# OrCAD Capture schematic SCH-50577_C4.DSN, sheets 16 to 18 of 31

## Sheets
16 16 PHY1_RGMII: size C
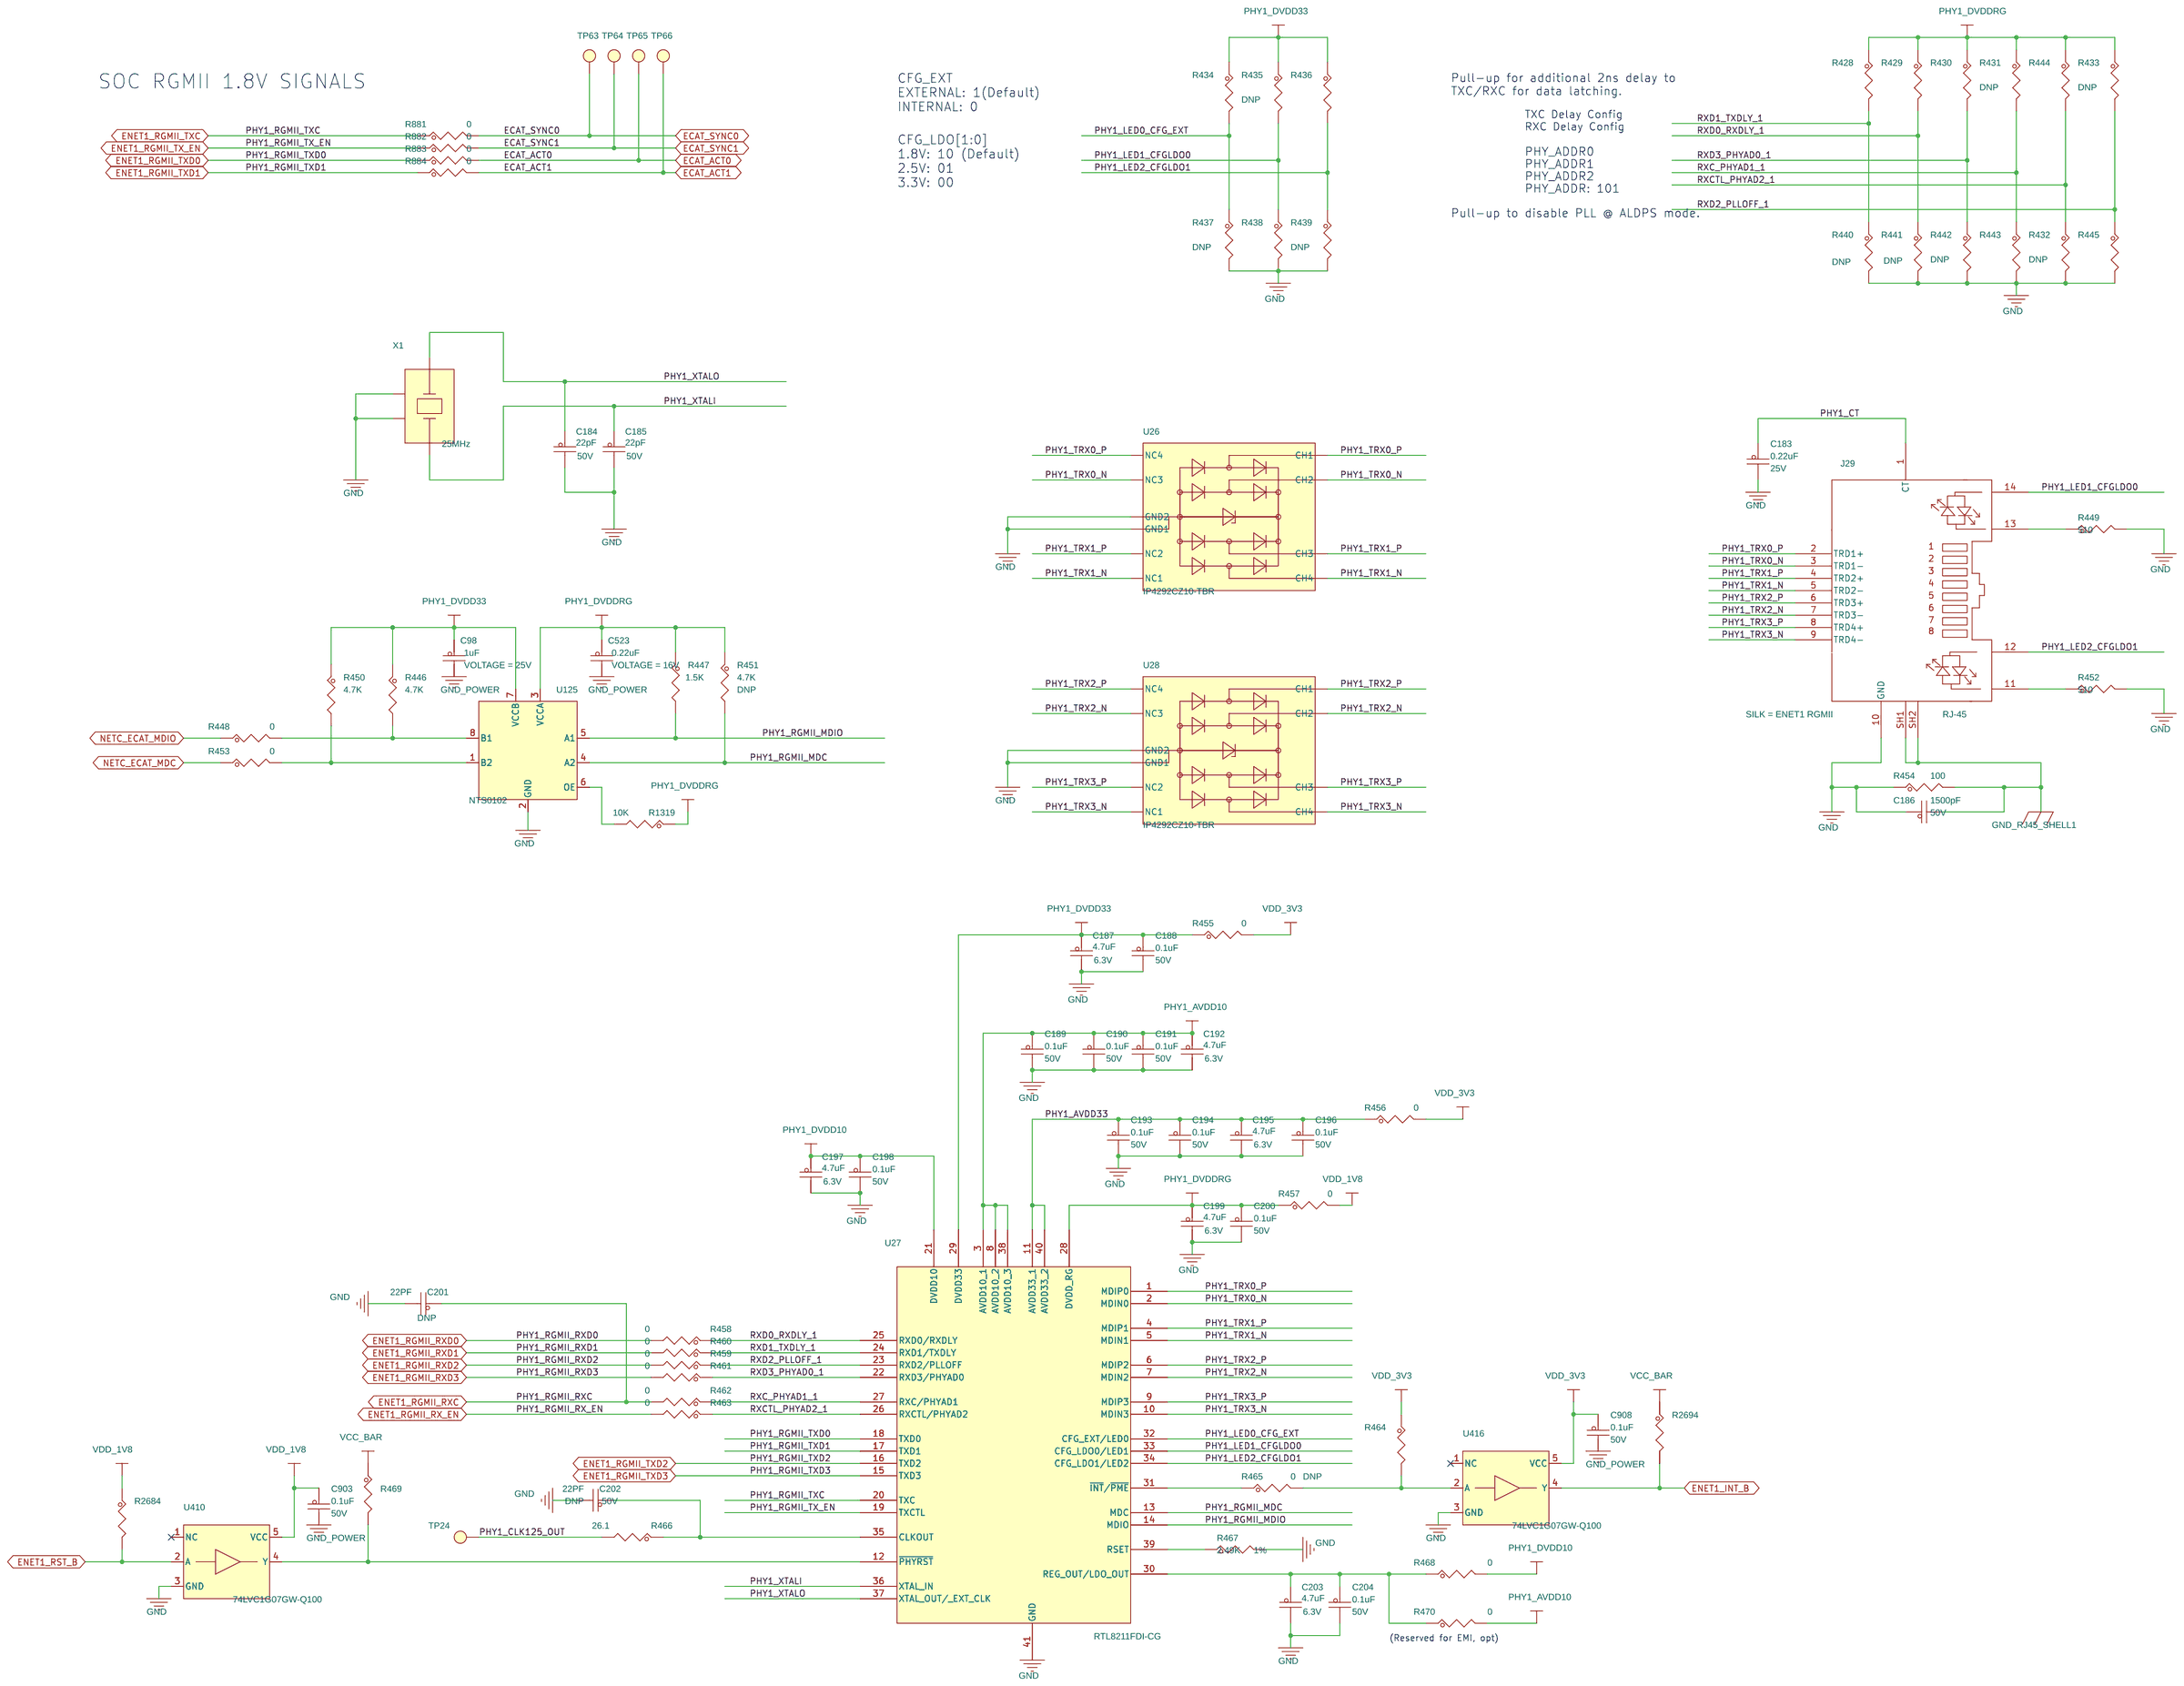
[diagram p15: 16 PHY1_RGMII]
17 17 PHY2_RGMII: size C
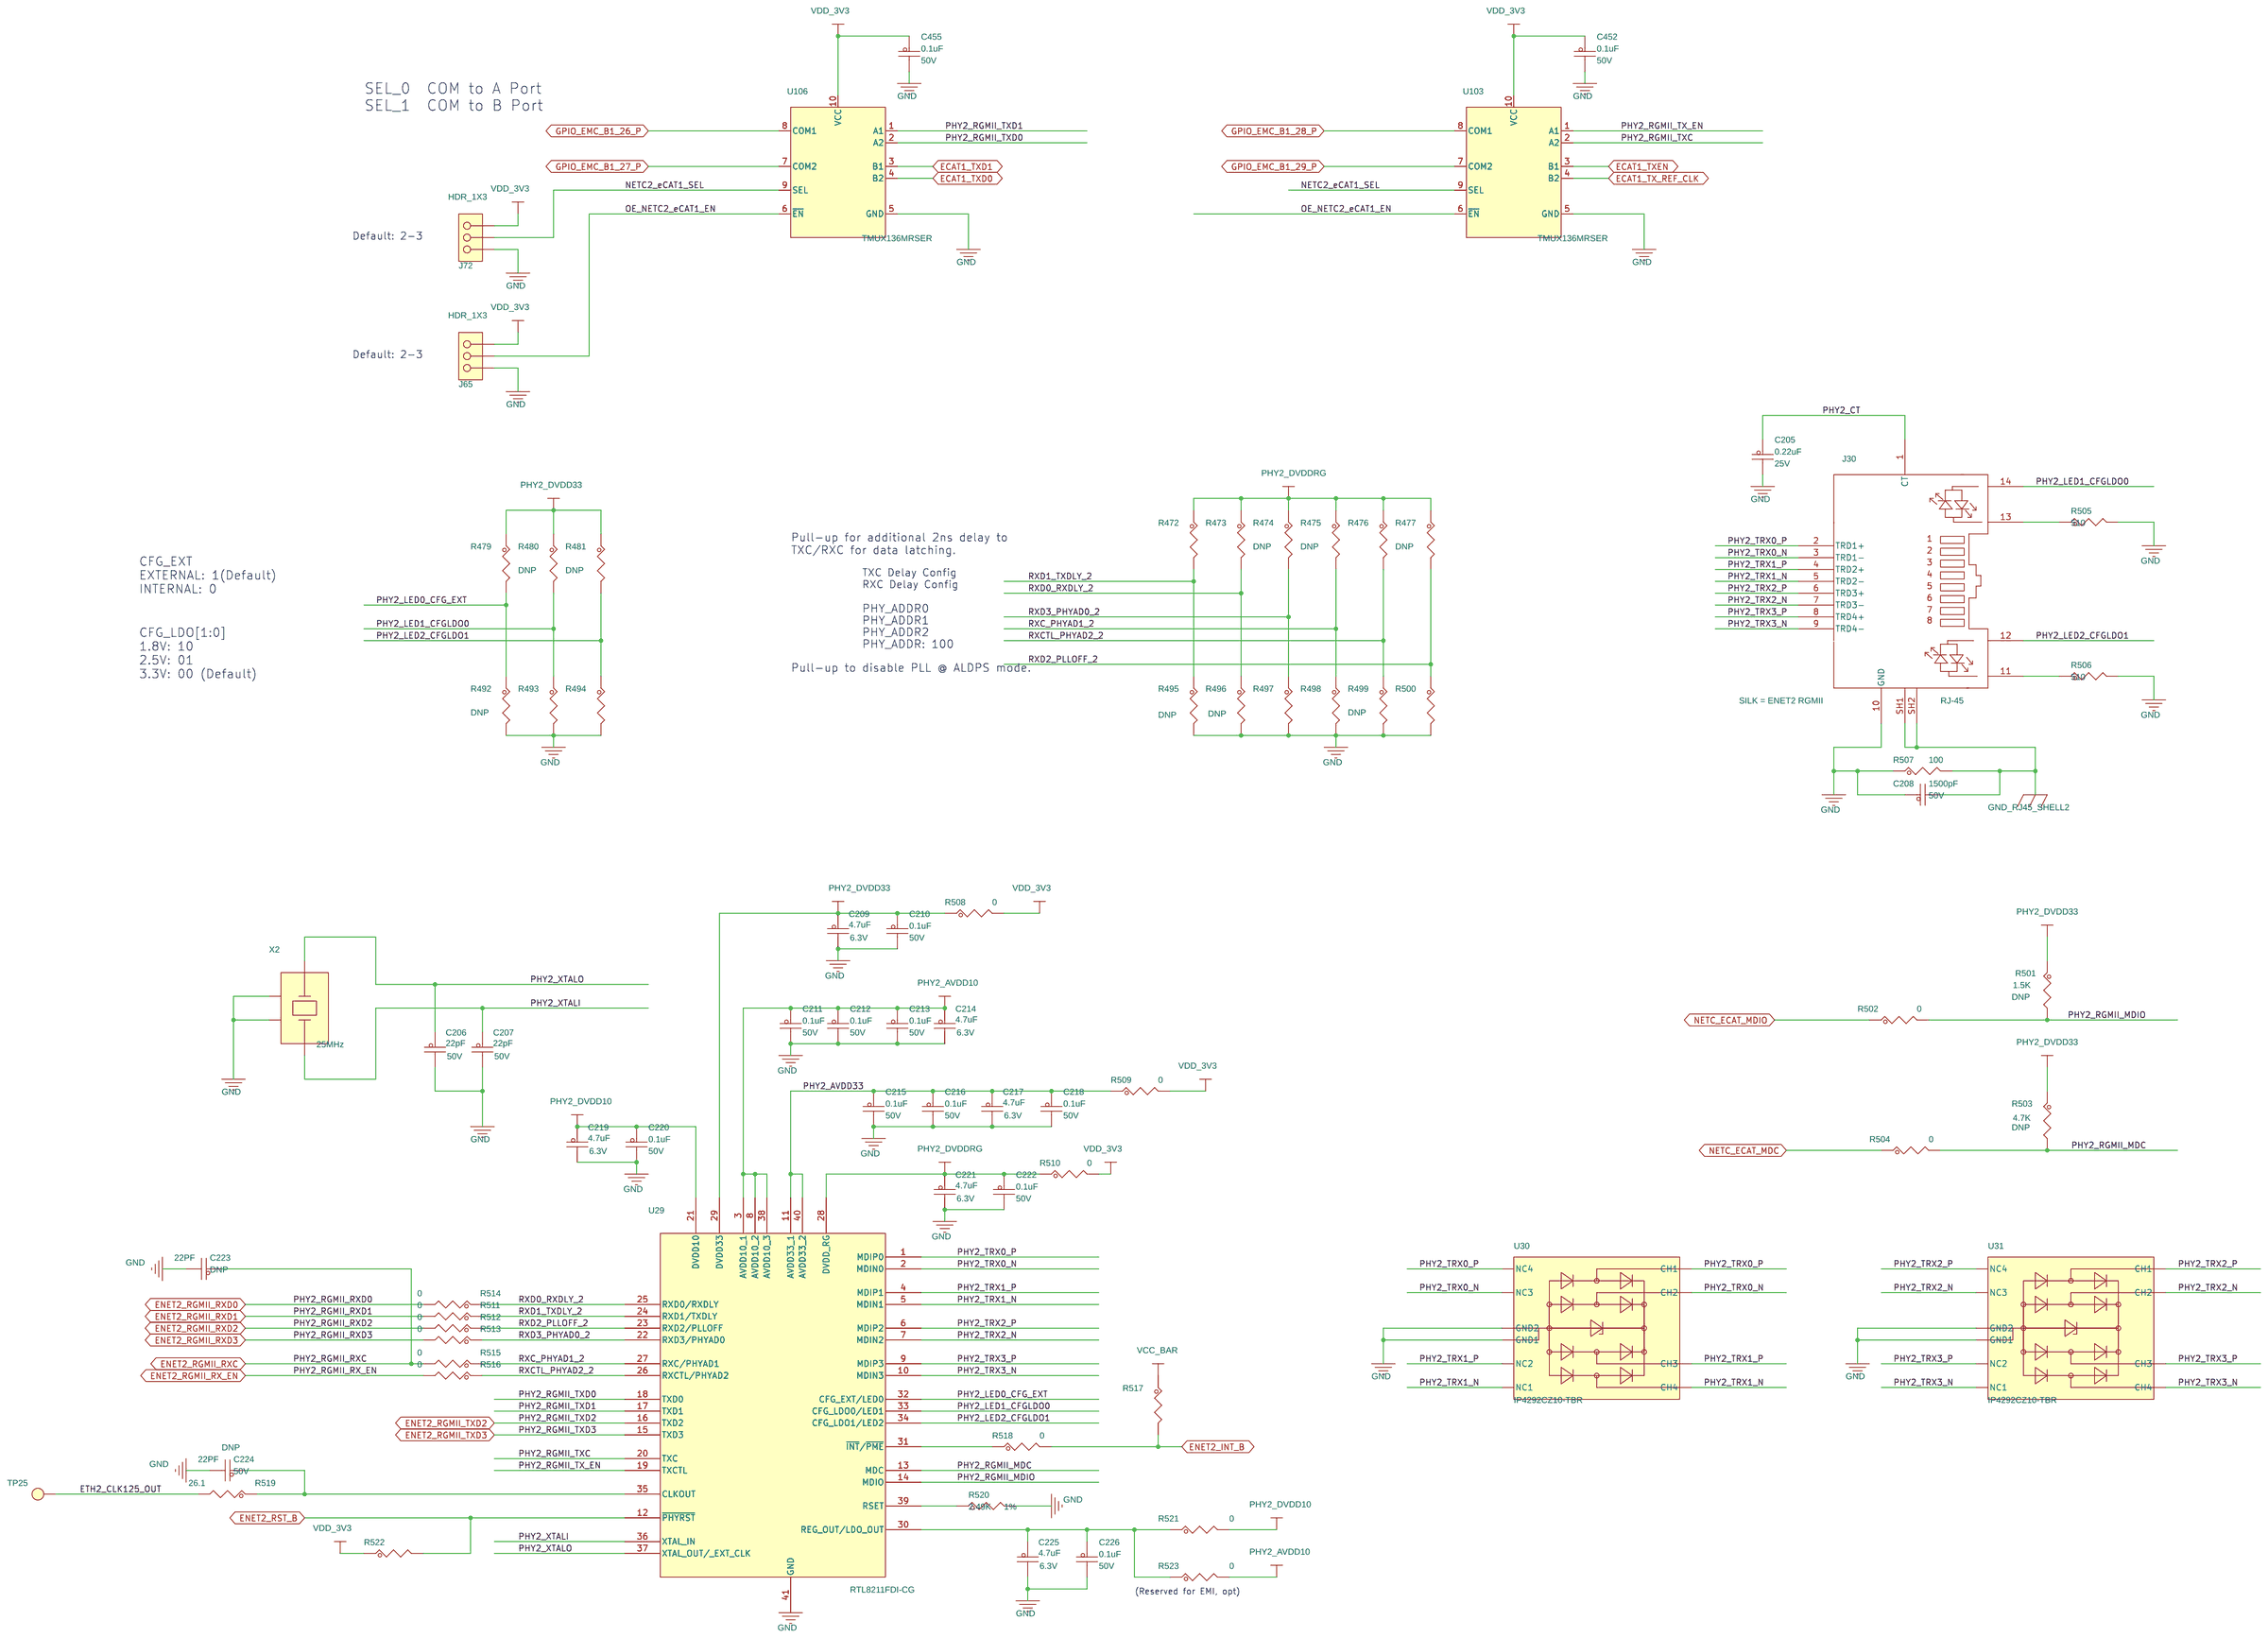
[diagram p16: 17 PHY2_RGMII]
18 18 PHY3_RGMII: size C
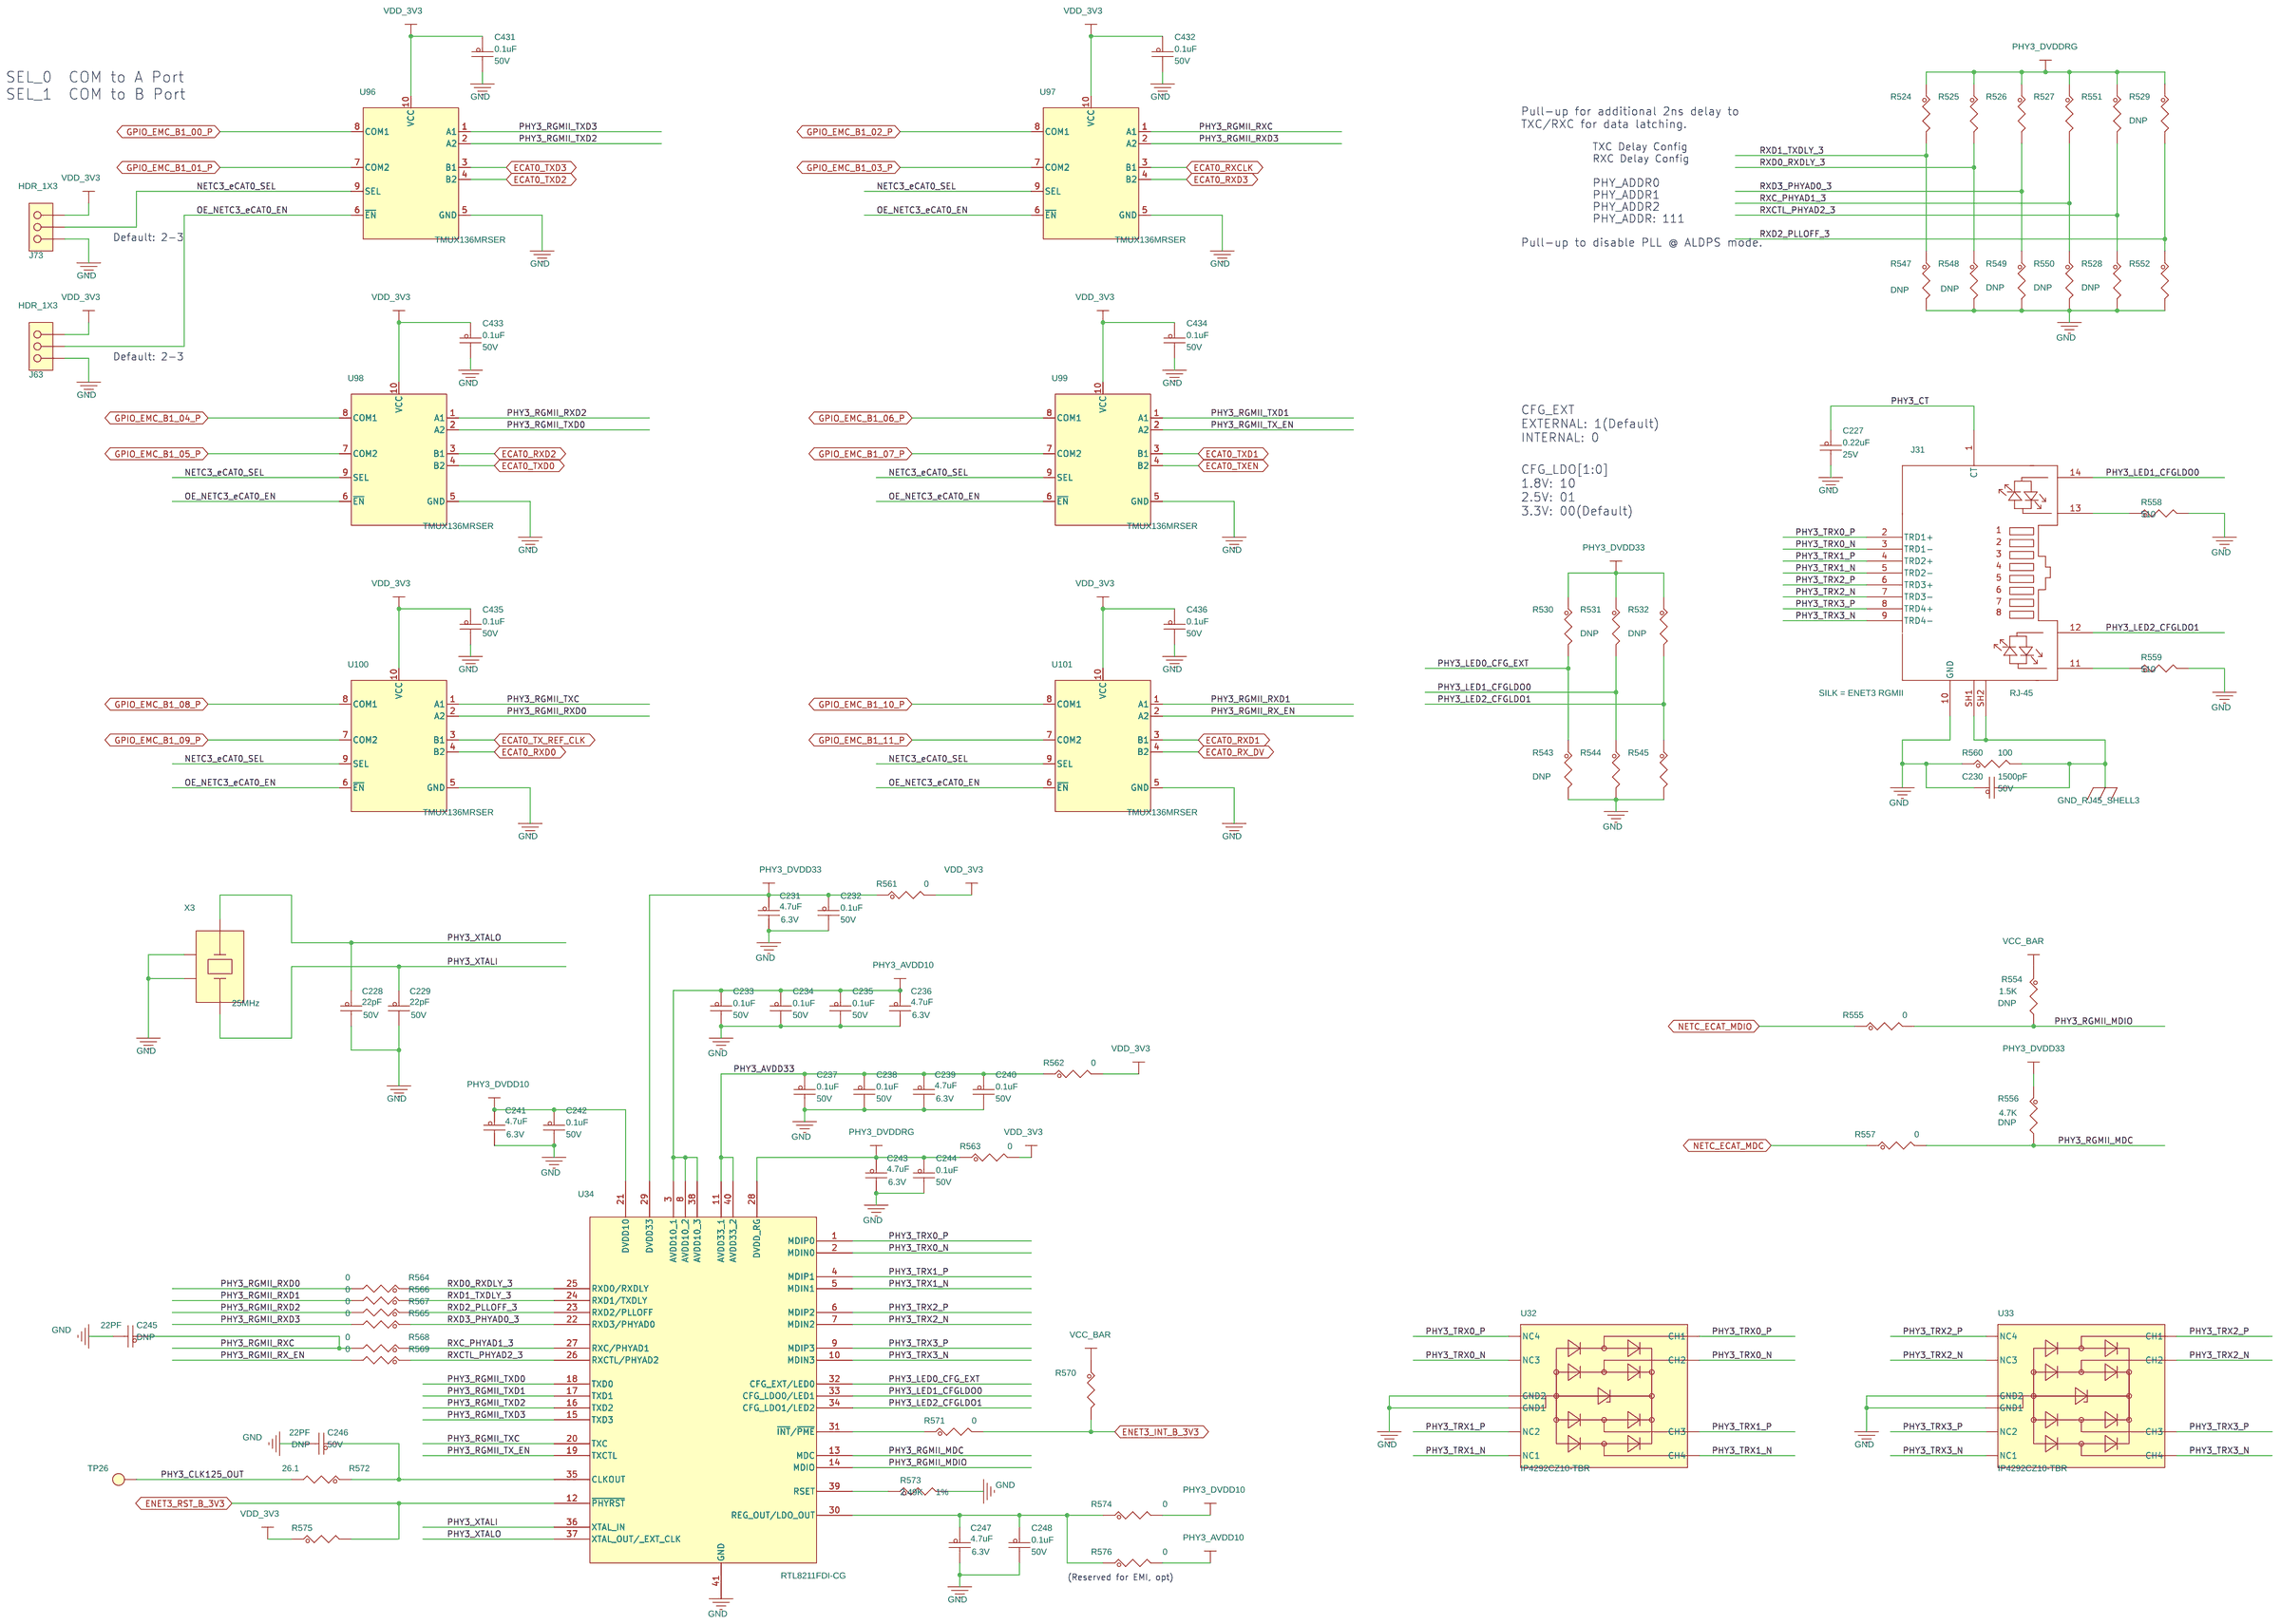
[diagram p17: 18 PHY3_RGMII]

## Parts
sheet 16 PHY1_RGMII
C98  1uF  [cc0402_tol0p2]
C183  0.22uF  [0402_CC]
C184  22pF  [0402_CC]
C185  22pF  [0402_CC]
C186  1500pF  [0402_CC]
C187  4.7uF  [cc0402_tol0p15]
C188  0.1uF  [0402_CC]
C189  0.1uF  [0402_CC]
C190  0.1uF  [0402_CC]
C191  0.1uF  [0402_CC]
C192  4.7uF  [cc0402_tol0p15]
C193  0.1uF  [0402_CC]
C194  0.1uF  [0402_CC]
C195  4.7uF  [cc0402_tol0p15]
C196  0.1uF  [0402_CC]
C197  4.7uF  [cc0402_tol0p15]
C198  0.1uF  [0402_CC]
C199  4.7uF  [cc0402_tol0p15]
C200  0.1uF  [0402_CC]
C201  22PF  [0402_CC]
C202  22PF  [0402_CC]
C203  4.7uF  [cc0402_tol0p15]
C204  0.1uF  [0402_CC]
C523  0.22uF  [0402_CC]
C903  0.1uF  [0402_CC]
C908  0.1uF  [0402_CC]
J29  RJ-45  [con_rj45_10_2led_th]
R428  4.7K  [0402_CC]
R429  4.7K  [0402_CC]
R430  4.7K  [0402_CC]
R431  4.7K  [0402_CC]
R432  4.7K  [0402_CC]
R433  4.7K  [0402_CC]
R434  4.7K  [0402_CC]
R435  4.7K  [0402_CC]
R436  4.7K  [0402_CC]
R437  4.7K  [0402_CC]
R438  4.7K  [0402_CC]
R439  4.7K  [0402_CC]
R440  4.7K  [0402_CC]
R441  4.7K  [0402_CC]
R442  4.7K  [0402_CC]
R443  4.7K  [0402_CC]
R444  4.7K  [0402_CC]
R445  4.7K  [0402_CC]
R446  4.7K  [0402_CC]
R447  1.5K  [0402_CC]
R448  0  [0402_CC]
R449  510  [0402_CC]
R450  4.7K  [0402_CC]
R451  4.7K  [0402_CC]
R452  510  [0402_CC]
R453  0  [0402_CC]
R454  100  [0402_CC]
R455  0  [0402_CC]
R456  0  [0402_CC]
R457  0  [0402_CC]
R458  0  [0402_CC]
R459  0  [0402_CC]
R460  0  [0402_CC]
R461  0  [0402_CC]
R462  0  [0402_CC]
R463  0  [0402_CC]
R464  4.7K  [0402_CC]
R465  0  [0402_CC]
R466  26.1  [0402_CC]
R467  2.49K  [0402_CC]
R468  0  [RC0603_OV]
R469  4.7K  [0402_CC]
R470  0  [RC0603_OV]
R881  0  [0402_CC]
R882  0  [0402_CC]
R883  0  [0402_CC]
R884  0  [0402_CC]
R1319  10K  [0402_CC]
R2684  10K  [0402_CC]
R2694  4.7K  [0402_CC]
TP24  TP_35MIL  [testpoint_35mil]
TP63  TP_35MIL  [testpoint_35mil]
TP64  TP_35MIL  [testpoint_35mil]
TP65  TP_35MIL  [testpoint_35mil]
TP66  TP_35MIL  [testpoint_35mil]
U26  IP4292CZ10-TBR  [xson10_0p5_1p1x2p6mm]
U27  RTL8211FDI-CG  [qfn40_0p4_5x5mm]
U28  IP4292CZ10-TBR  [xson10_0p5_1p1x2p6mm]
U125  NTS0102  [tssop8_a]
U410  74LVC1G07GW-Q100  [sc70-5]
U416  74LVC1G07GW-Q100  [sc70-5]
X1  25MHz  [xtal4_5p2x3p4mm_sm]
sheet 17 PHY2_RGMII
C205  0.22uF  [0402_CC]
C206  22pF  [0402_CC]
C207  22pF  [0402_CC]
C208  1500pF  [0402_CC]
C209  4.7uF  [cc0402_tol0p15]
C210  0.1uF  [0402_CC]
C211  0.1uF  [0402_CC]
C212  0.1uF  [0402_CC]
C213  0.1uF  [0402_CC]
C214  4.7uF  [cc0402_tol0p15]
C215  0.1uF  [0402_CC]
C216  0.1uF  [0402_CC]
C217  4.7uF  [cc0402_tol0p15]
C218  0.1uF  [0402_CC]
C219  4.7uF  [cc0402_tol0p15]
C220  0.1uF  [0402_CC]
C221  4.7uF  [cc0402_tol0p15]
C222  0.1uF  [0402_CC]
C223  22PF  [0402_CC]
C224  22PF  [0402_CC]
C225  4.7uF  [cc0402_tol0p15]
C226  0.1uF  [0402_CC]
C452  0.1uF  [0402_CC]
C455  0.1uF  [0402_CC]
J30  RJ-45  [con_rj45_10_2led_th]
J65  HDR_1X3  [HDR103]
J72  HDR_1X3  [HDR103]
R472  4.7K  [0402_CC]
R473  4.7K  [0402_CC]
R474  4.7K  [0402_CC]
R475  4.7K  [0402_CC]
R476  4.7K  [0402_CC]
R477  4.7K  [0402_CC]
R479  4.7K  [0402_CC]
R480  4.7K  [0402_CC]
R481  4.7K  [0402_CC]
R492  4.7K  [0402_CC]
R493  4.7K  [0402_CC]
R494  4.7K  [0402_CC]
R495  4.7K  [0402_CC]
R496  4.7K  [0402_CC]
R497  4.7K  [0402_CC]
R498  4.7K  [0402_CC]
R499  4.7K  [0402_CC]
R500  4.7K  [0402_CC]
R501  1.5K  [0402_CC]
R502  0  [0402_CC]
R503  4.7K  [0402_CC]
R504  0  [0402_CC]
R505  510  [0402_CC]
R506  510  [0402_CC]
R507  100  [0402_CC]
R508  0  [0402_CC]
R509  0  [0402_CC]
R510  0  [0402_CC]
R511  0  [0402_CC]
R512  0  [0402_CC]
R513  0  [0402_CC]
R514  0  [0402_CC]
R515  0  [0402_CC]
R516  0  [0402_CC]
R517  4.7K  [0402_CC]
R518  0  [0402_CC]
R519  26.1  [0402_CC]
R520  2.49K  [0402_CC]
R521  0  [RC0603_OV]
R522  4.7K  [0402_CC]
R523  0  [RC0603_OV]
TP25  TP_35MIL  [testpoint_35mil]
U29  RTL8211FDI-CG  [qfn40_0p4_5x5mm]
U30  IP4292CZ10-TBR  [xson10_0p5_1p1x2p6mm]
U31  IP4292CZ10-TBR  [xson10_0p5_1p1x2p6mm]
U103  TMUX136MRSER  [uqfn10_0p5_2p05x1p55]
U106  TMUX136MRSER  [uqfn10_0p5_2p05x1p55]
X2  25MHz  [xtal4_5p2x3p4mm_sm]
sheet 18 PHY3_RGMII
C227  0.22uF  [0402_CC]
C228  22pF  [0402_CC]
C229  22pF  [0402_CC]
C230  1500pF  [0402_CC]
C231  4.7uF  [cc0402_tol0p15]
C232  0.1uF  [0402_CC]
C233  0.1uF  [0402_CC]
C234  0.1uF  [0402_CC]
C235  0.1uF  [0402_CC]
C236  4.7uF  [cc0402_tol0p15]
C237  0.1uF  [0402_CC]
C238  0.1uF  [0402_CC]
C239  4.7uF  [cc0402_tol0p15]
C240  0.1uF  [0402_CC]
C241  4.7uF  [cc0402_tol0p15]
C242  0.1uF  [0402_CC]
C243  4.7uF  [cc0402_tol0p15]
C244  0.1uF  [0402_CC]
C245  22PF  [0402_CC]
C246  22PF  [0402_CC]
C247  4.7uF  [cc0402_tol0p15]
C248  0.1uF  [0402_CC]
C431  0.1uF  [0402_CC]
C432  0.1uF  [0402_CC]
C433  0.1uF  [0402_CC]
C434  0.1uF  [0402_CC]
C435  0.1uF  [0402_CC]
C436  0.1uF  [0402_CC]
J31  RJ-45  [con_rj45_10_2led_th]
J63  HDR_1X3  [HDR103]
J73  HDR_1X3  [HDR103]
R524  4.7K  [0402_CC]
R525  4.7K  [0402_CC]
R526  4.7K  [0402_CC]
R527  4.7K  [0402_CC]
R528  4.7K  [0402_CC]
R529  4.7K  [0402_CC]
R530  4.7K  [0402_CC]
R531  4.7K  [0402_CC]
R532  4.7K  [0402_CC]
R543  4.7K  [0402_CC]
R544  4.7K  [0402_CC]
R545  4.7K  [0402_CC]
R547  4.7K  [0402_CC]
R548  4.7K  [0402_CC]
R549  4.7K  [0402_CC]
R550  4.7K  [0402_CC]
R551  4.7K  [0402_CC]
R552  4.7K  [0402_CC]
R554  1.5K  [0402_CC]
R555  0  [0402_CC]
R556  4.7K  [0402_CC]
R557  0  [0402_CC]
R558  510  [0402_CC]
R559  510  [0402_CC]
R560  100  [0402_CC]
R561  0  [0402_CC]
R562  0  [0402_CC]
R563  0  [0402_CC]
R564  0  [0402_CC]
R565  0  [0402_CC]
R566  0  [0402_CC]
R567  0  [0402_CC]
R568  0  [0402_CC]
R569  0  [0402_CC]
R570  4.7K  [0402_CC]
R571  0  [0402_CC]
R572  26.1  [0402_CC]
R573  2.49K  [0402_CC]
R574  0  [RC0603_OV]
R575  4.7K  [0402_CC]
R576  0  [RC0603_OV]
TP26  TP_35MIL  [testpoint_35mil]
U32  IP4292CZ10-TBR  [xson10_0p5_1p1x2p6mm]
U33  IP4292CZ10-TBR  [xson10_0p5_1p1x2p6mm]
U34  RTL8211FDI-CG  [qfn40_0p4_5x5mm]
U96  TMUX136MRSER  [uqfn10_0p5_2p05x1p55]
U97  TMUX136MRSER  [uqfn10_0p5_2p05x1p55]
U98  TMUX136MRSER  [uqfn10_0p5_2p05x1p55]
U99  TMUX136MRSER  [uqfn10_0p5_2p05x1p55]
U100  TMUX136MRSER  [uqfn10_0p5_2p05x1p55]
U101  TMUX136MRSER  [uqfn10_0p5_2p05x1p55]
X3  25MHz  [xtal4_5p2x3p4mm_sm]

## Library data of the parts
C98 = CAP_NP: CAP CER 1uF 25V 10% X6S AEC-Q200 0402; AGILE_PN: 150-80570; CAD_APPROVED: Yes; FPLIST: cc0402_tol0p2,cc0402_tol0p2_ov,0402_cc_nsp; HEIGHT: 0.7MM; MFG_NAME01: MURATA; MFG_PN01: GRT155C81E105KE13D; Package Size: 1.1x0.6x0.6MM; Package Type: 0402; ROHS: Yes; Temp Range: -55°C to +105°C; Tolerance: 10%; VOLTAGE: 25V
C183 C205 C227 = CAP_NP: CAP CER 0.22uF 25V 10% X6S AEC-Q200 0402; AGILE_PN: 150-79689; CAD_APPROVED: Yes; FPLIST: CC0402_25,CC0402_HD,0402_CC,capc0402_l; HEIGHT: 0.55MM; MFG_NAME01: MURATA; MFG_PN01: GRT155C81E224KE01; Package Size: 0402; ROHS: Yes; Tolerance: 10%; VOLTAGE: 25V
C184 C185 C206 C207 C228 C229 = CAP_NP: CAP CER 22pF 50V 2% C0G HIGH-Q 0402; AGILE_PN: 150-79896; CAD_APPROVED: Yes; FPLIST: CC0402_25,CC0402_HD,0402_CC,capc0402_l; HEIGHT: 0.55MM; MFG_NAME01: MURATA; MFG_PN01: GJM1555C1H220GB01D; Package Size: 0402; Package Type: 180mm Reel PAPER W8P2; ROHS: Yes; Temp Range: -55 to +125°C; Tolerance: 2%; VOLTAGE: 50V
C186 C208 C230 = CAP_NP: CAP CER 1500PF 50V 10% X7R 0402; AGILE_PN: 150-76273; CAD_APPROVED: Yes; FPLIST: CC0402_25,CC0402_HD,0402_CC; HEIGHT: 0.55MM; MFG_NAME01: AVX; MFG_PN01: 04025C152KAT2A; ROHS: Yes; Tolerance: 10%; VOLTAGE: 50V
C187 C192 C195 C197 C199 C203 C209 C214 C217 C219 C221 C225 C231 C236 C239 C241 C243 C247 = CAP_NP: CAP CER 4.7uF 6.3V 20% X6S 0402; AGILE_PN: 150-81296; CAD_APPROVED: Yes; FPLIST: cc0402_tol0p15,cc0402_tol0p15_ov,cc0402_25_tol0p2,0402_cc_nsp; HEIGHT: 0.65MM; MFG_NAME01: MURATA; MFG_PN01: GRM155C80J475MEAA; Package Size: 0402 (1005 Metric); Package Type: SMD/SMT; ROHS: Yes; Rated Voltage: 6.3V; Temp Range: -55°C to +105°C; Tolerance: 20%; VOLTAGE: 6.3V
C188-C191 C193 C194 C196 C198 C200 C204 C210-C213 C215 C216 C218 C220 C222 C226 C232-C235 C237 C238 C240 C242 C244 C248 C431-C436 C452 C455 C903 C908 = CAP_NP: CAP CER 0.1uF 50V 10% X7R AEC-Q200 0402; AGILE_PN: 150-79461; CAD_APPROVED: Yes; FPLIST: CC0402_25,CC0402_HD,0402_CC,CC0402_18,capc0402_l; HEIGHT: 0.55MM; MFG_NAME01: MURATA; MFG_PN01: GCM155R71H104KE02D; Package Size: 0402; ROHS: Yes; Tolerance: 10%; VOLTAGE: 50V
C201 C202 C223 C224 C245 C246 = CAP_NP: CAP CER 22PF 50V 5% C0G 0402; AGILE_PN: 150-75266; ASSY_OPT: DNP; CAD_APPROVED: Yes; FPLIST: CC0402_25,CC0402_HD,0402_CC; HEIGHT: 0.635MM; MFG_NAME01: WURTH ELEKTRONIK EISOS GMBH & CO. KG (ELECTRONIC & ELECTROMEHANICAL COMP); MFG_PN01: 885012005057; ROHS: Yes; Temp Range: -55°C to 125°C; Temp_Range: -55°C to 125°C; Tolerance: 5%; VOLTAGE: 50V
C523 = CAP_NP: CAP CER 0.22uF 16V 10% X7R AEC-Q200 0402; AGILE_PN: 150-79207; CAD_APPROVED: Yes; FPLIST: CC0402_25,CC0402_HD,0402_CC,capc0402_l; HEIGHT: 0.55MM; MFG_NAME01: MURATA; MFG_PN01: GCM155R71C224KE02; Package Type: 0402; ROHS: Yes; Temp Range: -55°C to +125°C; Tolerance: 10%; VOLTAGE: 16V
J29 = RJ45_2_DUAL_LED_10P: CON 2X5 RJ-45 DUAL-LED SHLD RA TH 1.27MM SP 549H AU 120L; AGILE_PN: 210-81462; CAD_APPROVED: Yes; EN: 201-2-00061; HEIGHT: 13.95MM; MFG_NAME01: WURTH ELEKTRONIK EISOS GMBH & CO. KG (ELECTRONIC & ELECTROMEHANICAL COMP); MFG_PN01: 7499111446; ROHS: Yes; SILK: ENET1 RGMII; Temp Range: -40DegC to +85DegC; Temp_Range: -40DegC to +85DegC
R428-R430 R434 R436 R438 R443-R445 R464 R472 R473 R476 R479 R493 R494 R497 R498 R500 R517 R524-R527 R530 R544 R545 R551 R552 R570 R2694 = RES: RES MF 4.70K 1/16W 1% 0402; AGILE_PN: 470-75418; CAD_APPROVED: Yes; FPLIST: RC0402_25,RC0402_HD,0402_CC; HEIGHT: 0.4mm; MFG_NAME01: WALSIN TECHNOLOGY CORP.; MFG_PN01: WR04X4701FTL; ROHS: Yes; Tolerance: 1%; VOLTAGE: 1/16W
R431-R433 R435 R437 R439-R442 R474 R475 R477 R480 R481 R492 R495 R496 R499 R528 R529 R531 R532 R543 R547-R550 = RES: RES MF 4.70K 1/16W 1% 0402; AGILE_PN: 470-75418; ASSY_OPT: DNP; CAD_APPROVED: Yes; FPLIST: RC0402_25,RC0402_HD,0402_CC; HEIGHT: 0.4mm; MFG_NAME01: WALSIN TECHNOLOGY CORP.; MFG_PN01: WR04X4701FTL; ROHS: Yes; Tolerance: 1%; VOLTAGE: 1/16W
R446 R450 = RES: RES MF 4.7K 1/16W 5% 0402; AGILE_PN: 470-75626; CAD_APPROVED: Yes; FPLIST: RC0402_25,RC0402_HD,0402_CC; HEIGHT: 0.41mm; MFG_NAME01: NIC COMPONENTS CORP; MFG_PN01: NRCL04J472TRF; ROHS: Yes; Tolerance: 5%
R447 = RES: RES MF 1.5K 1/16W 5% 0402; AGILE_PN: 470-76303; CAD_APPROVED: Yes; FPLIST: RC0402_25,RC0402_HD,0402_CC; HEIGHT: 0.40 MM; MFG_NAME01: VISHAY INTERTECHNOLOGY; MFG_PN01: CRCW04021K50JNED; ROHS: Yes; Tolerance: 5%; VOLTAGE: 1/16W
R448 R453 R455 R456 R502 R504 R555 R557 R881-R884 = RES: RES MF ZERO OHM 1/16W 5% 0402; AGILE_PN: 470-75394; CAD_APPROVED: Yes; FPLIST: RC0402_25,RC0402_HD,RC0402_X2,0402_CC; HEIGHT: 0.45 MM; MFG_NAME01: YAGEO AMERICA; MFG_PN01: RC0402JR-070RL; ROHS: Yes; Tolerance: 5%; VOLTAGE: 1/16W
R449 R452 R505 R506 R558 R559 = RES: RES MF 510 OHM 1/16W 1% 0402; AGILE_PN: 470-80835; CAD_APPROVED: Yes; FPLIST: RC0402_25,RC0402_HD,0402_CC; HEIGHT: 0.4MM; MFG_NAME01: WALSIN TECHNOLOGY CORP.; MFG_PN01: WR04X5100FTL; ROHS: Yes; Tolerance: 1%
R451 R503 R556 = RES: RES MF 4.7K 1/16W 5% 0402; AGILE_PN: 470-75626; ASSY_OPT: DNP; CAD_APPROVED: Yes; FPLIST: RC0402_25,RC0402_HD,0402_CC; HEIGHT: 0.41mm; MFG_NAME01: NIC COMPONENTS CORP; MFG_PN01: NRCL04J472TRF; ROHS: Yes; Tolerance: 5%
R454 R507 R560 = RES: RES MF 100 OHM 1/16W 5% 0402; AGILE_PN: 470-75591; CAD_APPROVED: Yes; FPLIST: RC0402_25,RC0402_HD,RC0402_X2,0402_CC; HEIGHT: 0.45mm; MFG_NAME01: NIC COMPONENTS CORP; MFG_PN01: NRCL04J101TRF; ROHS: Yes; Tolerance: 5%
R457 R508-R510 R561-R563 = RES: RES MF ZERO OHM 1/16W 5% 0402; AGILE_PN: 470-75394; CAD_APPROVED: Yes; FPLIST: RC0402_25,RC0402_HD,RC0402_X2,0402_CC; HEIGHT: 0.45 MM; MFG_NAME01: ROHM; MFG_PN01: MCR01MZPJ000; ROHS: Yes; Tolerance: 5%; VOLTAGE: 1/16W
R458-R463 = RES: RES MF ZERO OHM 1/16W 5% 0402; AGILE_PN: 470-75394; CAD_APPROVED: Yes; FPLIST: RC0402_25,RC0402_HD,RC0402_X2,0402_CC; HEIGHT: 0.45 MM; MFG_NAME01: YAGEO AMERICA; MFG_PN01: RC0402JR-070RL; ROHS: Yes; SIGNAL_MODEL: DEFAULT_RESISTOR_33.000000OHM_2_1; TOL: 5%; Tolerance: 5%; VOLTAGE: 1/16W
R465 = RES: RES MF ZERO OHM 1/16W 5% 0402; AGILE_PN: 470-75394; ASSY_OPT: DNP; CAD_APPROVED: Yes; FPLIST: RC0402_25,RC0402_HD,RC0402_X2,0402_CC; HEIGHT: 0.45 MM; MFG_NAME01: YAGEO AMERICA; MFG_PN01: RC0402JR-070RL; ROHS: Yes; TOL: 5%; Tolerance: 5%; VOLTAGE: 1/16W
R466 R519 R572 = RES: RES MF 26.1 OHM 1/10W 1% AEC-Q200 0402; AGILE_PN: 470-30681; CAD_APPROVED: Yes; FPLIST: RC0402_25,RC0402_HD,0402_CC; HEIGHT: 0.40 MM; MFG_NAME01: KOA SPEER; MFG_PN01: RK73H1ETTP26R1F; ROHS: Yes; Temp Range: -55C to +155C; Temp_Range: -55C to +155C; Tolerance: 1%
R467 R520 R573 = RES: RES MF 2.49K  1/10W 1% AEC-Q200 0402; AGILE_PN: 470-30877; CAD_APPROVED: Yes; FPLIST: RC0402_25,RC0402_HD,0402_CC; HEIGHT: 0.40 MM; MFG_NAME01: KOA SPEER; MFG_PN01: RK73H1ETTP2491F; ROHS: Yes; SIGNAL_MODEL: DEFAULT_RESISTOR_2490OHM_2_1; Temp Range: -55C to +155C; Temp_Range: -55C to +155C; Tolerance: 1%; VOLTAGE: 50V
R468 R470 R521 R523 R574 R576 = RES: RES MF ZERO OHM 1/10W -- 0603; AGILE_PN: 470-80866; CAD_APPROVED: Yes; FPLIST: RC0603_OV,RC0603,R603-X2,0603_CC; HEIGHT: 0.6MM; MFG_NAME01: YAGEO AMERICA; MFG_PN01: RC0603FR-070RL; ROHS: Yes; SIGNAL_MODEL: DEFAULT_RESISTOR_0.001OHM_2_1; Temp Range: –55 °C to +155 °C; Temp_Range: –55 °C to +155 °C
R469 R522 R575 = RES: RES MF 4.70K 1/16W 1% 0402; AGILE_PN: 470-75418; CAD_APPROVED: Yes; FPLIST: RC0402_25,RC0402_HD,0402_CC; HEIGHT: 0.4mm; MFG_NAME01: WALSIN TECHNOLOGY CORP.; MFG_PN01: WR04X4701FTL; ROHS: Yes; TOL: 1%; Tolerance: 1%; VOLTAGE: 1/16W
R1319 = RES: RES MF 10K OHM 5% 1/10W AEC-Q200 0402; AGILE_PN: 470-81195; CAD_APPROVED: Yes; FPLIST: RC0402_25,RC0402_HD,0402_CC; HEIGHT: 0.4 MM; MFG_NAME01: PANASONIC; MFG_PN01: ERJ-2GEJ103X; ROHS: Yes
R2684 = RES: RES MF 10K 1/16W 5% 0402; AGILE_PN: 470-75557; CAD_APPROVED: Yes; FPLIST: RC0402_25,RC0402_HD,0402_CC; HEIGHT: 0.4 MM; MFG_NAME01: VISHAY INTERTECHNOLOGY; MFG_PN01: CRCW040210K0JNED; ROHS: Yes; TOL: 5%; Tolerance: 5%
TP24-TP26 TP63-TP66 = T_POINT_R: TEST POINT PAD .035 SMT, no part to order; AGILE_PN: 510-75618; CAD_APPROVED: Yes; HEIGHT: 0.1MM; ROHS: Yes
U26 U28 U30-U33 = PUSB3F96_DFN2510A_10P: DIODE ESD TVS ARRAY USB2 USB3 5.5V 4A DFN2510A-10; AGILE_PN: 480-79837; CAD_APPROVED: Yes; EN: 301-0-01726; HEIGHT: 0.5MM; MFG_NAME01: NEXPERIA; MFG_PN01: IP4292CZ10-TBR,115; ROHS: Yes; Temp Range: -40C to +85C; Temp_Range: -40C to +85C
U27 U29 U34 = RTL8211FD-40P: IC XCVR ETH Industrial 10/100/1000MBPS RGMII 3.3V/2.5V/1.8V/1.5V QFN40; AGILE_PN: 312-81304; CAD_APPROVED: Yes; HEIGHT: 0.9MM; MFG_NAME01: REALTEK SEMICONDUCTOR; ROHS: Yes; VOLTAGE: 3.3V/2.5V/1.8V/1.5V
U125 = NTB0102_8P: IC XCVR 2-BIT 1.65-3.6V/2.3-5.5V TSSOP8; AGILE_PN: 312-80889; CAD_APPROVED: Yes; HEIGHT: 1.1MM; MFG_NAME01: NXP SEMICONDUCTORS; MFG_PN01: NTS0102DP; ROHS: Yes; VOLTAGE: 1.65-3.6V/2.3-5.5V
U410 U416 = 74AUP1G07GW: IC BUF NON-INV SGL 1.65-5.5V AEC-Q100 TSSOP5; 3D_Mechanical_Footprint_File: ftp://fcl.am.freescale.net/ALLEGRO/step/sc70-5.STEP; AGILE_PN: 312-82179; CAD_APPROVED: Yes; HEIGHT: 1.1MM; MFG_NAME01: NEXPERIA; MFG_PN01: 74LVC1G07GW-Q100H; ROHS: Yes; Temp Range: -40 to +125C; VOLTAGE: 1.65-5.5V
X1-X3 = XTAL_13: XTAL 25MHz 13PF 5x3.2mm SMT; AGILE_PN: 230-78201; CAD_APPROVED: Yes; EN: 108-1-00013; HEIGHT: 1MM; MFG_NAME01: CTS; MFG_PN01: 405C35B25M00000; ROHS: Yes; Temp Range: -20C to +70C; Temp_Range: -20C to +70C
J30 = RJ45_2_DUAL_LED_10P: CON 2X5 RJ-45 DUAL-LED SHLD RA TH 1.27MM SP 549H AU 120L; AGILE_PN: 210-81462; CAD_APPROVED: Yes; EN: 201-2-00061; HEIGHT: 13.95MM; MFG_NAME01: WURTH ELEKTRONIK EISOS GMBH & CO. KG (ELECTRONIC & ELECTROMEHANICAL COMP); MFG_PN01: 7499111446; ROHS: Yes; SILK: ENET2 RGMII; Temp Range: -40DegC to +85DegC; Temp_Range: -40DegC to +85DegC
J63 J65 J72 J73 = CONN_HDR_3X1: HDR 1X3 TH 100MIL SP 338H AU 98L; AGILE_PN: 210-81491; CAD_APPROVED: Yes; HEIGHT: 8.59MM; Jumper(Default): 2-3; MFG_NAME01: ANYTRONIC CORPORATION LIMITED; MFG_PN01: 0901S0203011N9T-31RF; ROHS: Yes; Temp Range: -55°C to +105°C; Temp_Range: -55°C to +105°C
R501 R554 = RES: RES MF 1.5K 1/16W 5% 0402; AGILE_PN: 470-76303; ASSY_OPT: DNP; CAD_APPROVED: Yes; FPLIST: RC0402_25,RC0402_HD,0402_CC; HEIGHT: 0.40 MM; MFG_NAME01: VISHAY INTERTECHNOLOGY; MFG_PN01: CRCW04021K50JNED; ROHS: Yes; Tolerance: 5%; VOLTAGE: 1/16W
R511-R516 R564-R569 = RES: RES MF ZERO OHM 1/16W 5% 0402; AGILE_PN: 470-75394; CAD_APPROVED: Yes; FPLIST: RC0402_25,RC0402_HD,RC0402_X2,0402_CC; HEIGHT: 0.45 MM; MFG_NAME01: ROHM; MFG_PN01: MCR01MZPJ000; ROHS: Yes; SIGNAL_MODEL: DEFAULT_RESISTOR_33.000000OHM_2_1; TOL: 5%; Tolerance: 5%; VOLTAGE: 1/16W
R518 R571 = RES: RES MF ZERO OHM 1/16W 5% 0402; AGILE_PN: 470-75394; CAD_APPROVED: Yes; FPLIST: RC0402_25,RC0402_HD,RC0402_X2,0402_CC; HEIGHT: 0.45 MM; MFG_NAME01: ROHM; MFG_PN01: MCR01MZPJ000; ROHS: Yes; TOL: 5%; Tolerance: 5%; VOLTAGE: 1/16W
U96-U101 U103 U106 = TMUX136_UQFN10: IC DUAL SPDT POWER 6GHz 2.3-4.8V UQFN10; AGILE_PN: 315-81880; CAD_APPROVED: Yes; HEIGHT: 0.6MM; MFG_NAME01: TEXAS INSTRUMENTS; ROHS: Yes; Temp Range: -40C to +85C; VOLTAGE: 2.3-4.8V
J31 = RJ45_2_DUAL_LED_10P: CON 2X5 RJ-45 DUAL-LED SHLD RA TH 1.27MM SP 549H AU 120L; AGILE_PN: 210-81462; CAD_APPROVED: Yes; EN: 201-2-00061; HEIGHT: 13.95MM; MFG_NAME01: WURTH ELEKTRONIK EISOS GMBH & CO. KG (ELECTRONIC & ELECTROMEHANICAL COMP); MFG_PN01: 7499111446; ROHS: Yes; SILK: ENET3 RGMII; Temp Range: -40DegC to +85DegC; Temp_Range: -40DegC to +85DegC

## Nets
GND: C98.2 C183.2 C184.2 C185.2 C186.1 C187.2 C188.2 C189.2 C190.2 C191.2 C192.2 C193.2 C194.2 C195.2 C196.2 C197.2 C198.2 C199.2 C200.2 C201.2 C202.2 C203.2 C204.2 C205.2 C206.2 C207.2 C208.1 C209.2 C210.2 C211.2 C212.2 C213.2 C214.2 C215.2 C216.2 C217.2 C218.2 C219.2 C220.2 C221.2 C222.2 C223.2 C224.2 C225.2 C226.2 C227.2 C228.2 C229.2 C230.1 C231.2 C232.2 C233.2 C234.2 C235.2 C236.2 C237.2 C238.2 C239.2 C240.2 C241.2 C242.2 C243.2 C244.2 C245.2 C246.2 C247.2 C248.2 C431.2 C432.2 C433.2 C434.2 C435.2 C436.2 C452.2 C455.2 C523.2 C903.2 C908.2 J29.10(GND) J30.10(GND) J31.10(GND) J63.3 J65.3 J72.3 J73.3 R432.2 R437.2 R438.2 R439.2 R440.2 R441.2 R442.2 R443.2 R445.2 R449.2 R452.2 R454.1 R467.2 R492.2 R493.2 R494.2 R495.2 R496.2 R497.2 R498.2 R499.2 R500.2 R505.2 R506.2 R507.1 R520.2 R528.2 R543.2 R544.2 R545.2 R547.2 R548.2 R549.2 R550.2 R552.2 R558.2 R559.2 R560.1 R573.2 U26.3(GND1) U26.8(GND2) U27.41(GND) U28.3(GND1) U28.8(GND2) U29.41(GND) U30.3(GND1) U30.8(GND2) U31.3(GND1) U31.8(GND2) U32.3(GND1) U32.8(GND2) U33.3(GND1) U33.8(GND2) U34.41(GND) U96.5(GND) U97.5(GND) U98.5(GND) U99.5(GND) U100.5(GND) U101.5(GND) U103.5(GND) U106.5(GND) U125.2(GND) U410.3(GND) U416.3(GND) X1.2 X1.4 X2.2 X2.4 X3.2 X3.4 ; also on sheet 2 5 6 7 8 9 10 11 12 13 14 15 19 20 21 22 23 24 25 26 27 28 29 30 31
GND_RJ45_SHELL1: C186.2 J29.SH1 J29.SH2 R454.2
GND_RJ45_SHELL2: C208.2 J30.SH1 J30.SH2 R507.2
GND_RJ45_SHELL3: C230.2 J31.SH1 J31.SH2 R560.2
VDD_1V8: C903.1 R457.2 R2684.1 R2694.1 U410.5(VCC) ; also on sheet 6 7 8 9 14 21 22 24
ECAT0_RX_DV: U101.4(B2) ; also on sheet 31
ECAT0_RXCLK: U97.3(B1) ; also on sheet 31
ECAT0_RXD0: U100.4(B2) ; also on sheet 31
ECAT0_RXD1: U101.3(B1) ; also on sheet 31
ECAT0_RXD2: U98.3(B1) ; also on sheet 31
ECAT0_RXD3: U97.4(B2) ; also on sheet 31
ECAT0_TX_REF_CLK: U100.3(B1) ; also on sheet 31
ECAT0_TXD0: U98.4(B2) ; also on sheet 31
ECAT0_TXD1: U99.3(B1) ; also on sheet 31
ECAT0_TXD2: U96.4(B2) ; also on sheet 31
ECAT0_TXD3: U96.3(B1) ; also on sheet 31
ECAT0_TXEN: U99.4(B2) ; also on sheet 31
ECAT1_TX_REF_CLK: U103.4(B2) ; also on sheet 30
ECAT1_TXD0: U106.4(B2) ; also on sheet 30
ECAT1_TXD1: U106.3(B1) ; also on sheet 30
ECAT1_TXEN: U103.3(B1) ; also on sheet 30
ECAT_ACT0: R883.2 TP65.1(TP) ; also on sheet 26
ECAT_ACT1: R884.2 TP66.1(TP) ; also on sheet 26
ECAT_SYNC0: R881.2 TP63.1(TP) ; also on sheet 26
ECAT_SYNC1: R882.2 TP64.1(TP) ; also on sheet 26
ENET1_INT_B: R2694.2 U416.4(Y) ; also on sheet 8
ENET1_RGMII_RX_EN: R463.2 ; also on sheet 8
ENET1_RGMII_RXC: C201.1 R462.2 ; also on sheet 8
ENET1_RGMII_RXD0: R458.2 ; also on sheet 8
ENET1_RGMII_RXD1: R460.2 ; also on sheet 8
ENET1_RGMII_RXD2: R459.2 ; also on sheet 8
ENET1_RGMII_RXD3: R461.2 ; also on sheet 8
ENET1_RGMII_TX_EN: R882.1 U27.19(TXCTL) ; also on sheet 8
ENET1_RGMII_TXC: R881.1 U27.20(TXC) ; also on sheet 8
ENET1_RGMII_TXD0: R883.1 U27.18(TXD0) ; also on sheet 8
ENET1_RGMII_TXD1: R884.1 U27.17(TXD1) ; also on sheet 8
ENET1_RGMII_TXD2: U27.16(TXD2) ; also on sheet 8
ENET1_RGMII_TXD3: U27.15(TXD3) ; also on sheet 8
ENET1_RST_B: R2684.2 U410.2(A) ; also on sheet 8
ENET2_INT_B: R517.2 R518.2 ; also on sheet 8
ENET2_RGMII_RX_EN: R516.2 ; also on sheet 9
ENET2_RGMII_RXC: C223.1 R515.2 ; also on sheet 9
ENET2_RGMII_RXD0: R514.2 ; also on sheet 9
ENET2_RGMII_RXD1: R511.2 ; also on sheet 9
ENET2_RGMII_RXD2: R512.2 ; also on sheet 9
ENET2_RGMII_RXD3: R513.2 ; also on sheet 9
ENET2_RGMII_TXD2: U29.16(TXD2) ; also on sheet 9
ENET2_RGMII_TXD3: U29.15(TXD3) ; also on sheet 9
ENET2_RST_B: R522.2 U29.12(~{PHYRST}) ; also on sheet 8
ENET3_INT_B_3V3: R570.2 R571.2 ; also on sheet 8
ENET3_RST_B_3V3: R575.2 U34.12(~{PHYRST}) ; also on sheet 8
ETH2_CLK125_OUT: R519.2 TP25.1(TP)
GPIO_EMC_B1_00_P: U96.8(COM1) ; also on sheet 9
GPIO_EMC_B1_01_P: U96.7(COM2) ; also on sheet 9
GPIO_EMC_B1_02_P: U97.8(COM1) ; also on sheet 9
GPIO_EMC_B1_03_P: U97.7(COM2) ; also on sheet 9
GPIO_EMC_B1_04_P: U98.8(COM1) ; also on sheet 9
GPIO_EMC_B1_05_P: U98.7(COM2) ; also on sheet 9
GPIO_EMC_B1_06_P: U99.8(COM1) ; also on sheet 9
GPIO_EMC_B1_07_P: U99.7(COM2) ; also on sheet 9
GPIO_EMC_B1_08_P: U100.8(COM1) ; also on sheet 9
GPIO_EMC_B1_09_P: U100.7(COM2) ; also on sheet 9
GPIO_EMC_B1_10_P: U101.8(COM1) ; also on sheet 9
GPIO_EMC_B1_11_P: U101.7(COM2) ; also on sheet 9
GPIO_EMC_B1_26_P: U106.8(COM1) ; also on sheet 9
GPIO_EMC_B1_27_P: U106.7(COM2) ; also on sheet 9
GPIO_EMC_B1_28_P: U103.8(COM1) ; also on sheet 9
GPIO_EMC_B1_29_P: U103.7(COM2) ; also on sheet 9
NETC2_eCAT1_SEL: J72.2 U103.9(SEL) U106.9(SEL)
NETC3_eCAT0_SEL: J73.2 U96.9(SEL) U97.9(SEL) U98.9(SEL) U99.9(SEL) U100.9(SEL) U101.9(SEL)
NETC_ECAT_MDC: R453.1 R504.1 R557.1 ; also on sheet 8 29 30 31
NETC_ECAT_MDIO: R448.1 R502.1 R555.1 ; also on sheet 8 29 30 31
OE_NETC2_eCAT1_EN: J65.2 U103.6(~{EN}) U106.6(~{EN})
OE_NETC3_eCAT0_EN: J63.2 U96.6(~{EN}) U97.6(~{EN}) U98.6(~{EN}) U99.6(~{EN}) U100.6(~{EN}) U101.6(~{EN})
PHY1_AVDD10: C189.1 C190.1 C191.1 C192.1 R470.2 U27.3(AVDD10_1) U27.8(AVDD10_2) U27.38(AVDD10_3)
PHY1_AVDD33: C193.1 C194.1 C195.1 C196.1 R456.1 U27.11(AVDD33_1) U27.40(AVDD33_2)
PHY1_CLK125_OUT: R466.2 TP24.1(TP)
PHY1_CT: C183.1 J29.1(CT)
PHY1_DVDD10: C197.1 C198.1 R468.2 U27.21(DVDD10)
PHY1_DVDD33: C98.1 C187.1 C188.1 R434.1 R435.1 R436.1 R446.1 R450.1 R455.1 U27.29(DVDD33) U125.7(VCCB)
PHY1_DVDDRG: C199.1 C200.1 C523.1 R428.1 R429.1 R430.1 R431.1 R433.1 R444.1 R447.1 R451.1 R457.1 R1319.1 U27.28(DVDD_RG) U125.3(VCCA)
PHY1_LED0_CFG_EXT: R434.2 R437.1 U27.32(CFG_EXT/LED0)
PHY1_LED1_CFGLDO0: J29.14 R435.2 R438.1 U27.33(CFG_LDO0/LED1)
PHY1_LED2_CFGLDO1: J29.12 R436.2 R439.1 U27.34(CFG_LDO1/LED2)
PHY1_RGMII_MDC: R451.2 U27.13(MDC) U125.4(A2)
PHY1_RGMII_MDIO: R447.2 U27.14(MDIO) U125.5(A1)
PHY1_TRX0_N: J29.3(TRD1-) U26.2(CH2) U26.9(NC3) U27.2(MDIN0)
PHY1_TRX0_P: J29.2(TRD1+) U26.1(CH1) U26.10(NC4) U27.1(MDIP0)
PHY1_TRX1_N: J29.5(TRD2-) U26.5(CH4) U26.6(NC1) U27.5(MDIN1)
PHY1_TRX1_P: J29.4(TRD2+) U26.4(CH3) U26.7(NC2) U27.4(MDIP1)
PHY1_TRX2_N: J29.7(TRD3-) U27.7(MDIN2) U28.2(CH2) U28.9(NC3)
PHY1_TRX2_P: J29.6(TRD3+) U27.6(MDIP2) U28.1(CH1) U28.10(NC4)
PHY1_TRX3_N: J29.9(TRD4-) U27.10(MDIN3) U28.5(CH4) U28.6(NC1)
PHY1_TRX3_P: J29.8(TRD4+) U27.9(MDIP3) U28.4(CH3) U28.7(NC2)
PHY1_XTALI: C185.1 U27.36(XTAL_IN) X1.3
PHY1_XTALO: C184.1 U27.37(XTAL_OUT/_EXT_CLK) X1.1
PHY2_AVDD10: C211.1 C212.1 C213.1 C214.1 R523.2 U29.3(AVDD10_1) U29.8(AVDD10_2) U29.38(AVDD10_3)
PHY2_AVDD33: C215.1 C216.1 C217.1 C218.1 R509.1 U29.11(AVDD33_1) U29.40(AVDD33_2)
PHY2_CT: C205.1 J30.1(CT)
PHY2_DVDD10: C219.1 C220.1 R521.2 U29.21(DVDD10)
PHY2_DVDD33: C209.1 C210.1 R479.1 R480.1 R481.1 R501.1 R503.1 R508.1 U29.29(DVDD33)
PHY2_DVDDRG: C221.1 C222.1 R472.1 R473.1 R474.1 R475.1 R476.1 R477.1 R510.1 U29.28(DVDD_RG)
PHY2_LED0_CFG_EXT: R479.2 R492.1 U29.32(CFG_EXT/LED0)
PHY2_LED1_CFGLDO0: J30.14 R480.2 R493.1 U29.33(CFG_LDO0/LED1)
PHY2_LED2_CFGLDO1: J30.12 R481.2 R494.1 U29.34(CFG_LDO1/LED2)
PHY2_RGMII_MDC: R503.2 R504.2 U29.13(MDC)
PHY2_RGMII_MDIO: R501.2 R502.2 U29.14(MDIO)
PHY2_RGMII_TX_EN: U29.19(TXCTL) U103.1(A1)
PHY2_RGMII_TXC: U29.20(TXC) U103.2(A2)
PHY2_RGMII_TXD0: U29.18(TXD0) U106.2(A2)
PHY2_RGMII_TXD1: U29.17(TXD1) U106.1(A1)
PHY2_TRX0_N: J30.3(TRD1-) U29.2(MDIN0) U30.2(CH2) U30.9(NC3)
PHY2_TRX0_P: J30.2(TRD1+) U29.1(MDIP0) U30.1(CH1) U30.10(NC4)
PHY2_TRX1_N: J30.5(TRD2-) U29.5(MDIN1) U30.5(CH4) U30.6(NC1)
PHY2_TRX1_P: J30.4(TRD2+) U29.4(MDIP1) U30.4(CH3) U30.7(NC2)
PHY2_TRX2_N: J30.7(TRD3-) U29.7(MDIN2) U31.2(CH2) U31.9(NC3)
PHY2_TRX2_P: J30.6(TRD3+) U29.6(MDIP2) U31.1(CH1) U31.10(NC4)
PHY2_TRX3_N: J30.9(TRD4-) U29.10(MDIN3) U31.5(CH4) U31.6(NC1)
PHY2_TRX3_P: J30.8(TRD4+) U29.9(MDIP3) U31.4(CH3) U31.7(NC2)
PHY2_XTALI: C207.1 U29.36(XTAL_IN) X2.3
PHY2_XTALO: C206.1 U29.37(XTAL_OUT/_EXT_CLK) X2.1
PHY3_AVDD10: C233.1 C234.1 C235.1 C236.1 R576.2 U34.3(AVDD10_1) U34.8(AVDD10_2) U34.38(AVDD10_3)
PHY3_AVDD33: C237.1 C238.1 C239.1 C240.1 R562.1 U34.11(AVDD33_1) U34.40(AVDD33_2)
PHY3_CLK125_OUT: R572.2 TP26.1(TP)
PHY3_CT: C227.1 J31.1(CT)
PHY3_DVDD10: C241.1 C242.1 R574.2 U34.21(DVDD10)
PHY3_DVDD33: C231.1 C232.1 R530.1 R531.1 R532.1 R554.1 R556.1 R561.1 U34.29(DVDD33)
PHY3_DVDDRG: C243.1 C244.1 R524.1 R525.1 R526.1 R527.1 R529.1 R551.1 R563.1 U34.28(DVDD_RG)
PHY3_LED0_CFG_EXT: R530.2 R543.1 U34.32(CFG_EXT/LED0)
PHY3_LED1_CFGLDO0: J31.14 R531.2 R544.1 U34.33(CFG_LDO0/LED1)
PHY3_LED2_CFGLDO1: J31.12 R532.2 R545.1 U34.34(CFG_LDO1/LED2)
PHY3_RGMII_MDC: R556.2 R557.2 U34.13(MDC)
PHY3_RGMII_MDIO: R554.2 R555.2 U34.14(MDIO)
PHY3_RGMII_RX_EN: R569.2 U101.2(A2)
PHY3_RGMII_RXC: C245.1 R568.2 U97.1(A1)
PHY3_RGMII_RXD0: R564.2 U100.2(A2)
PHY3_RGMII_RXD1: R566.2 U101.1(A1)
PHY3_RGMII_RXD2: R567.2 U98.1(A1)
PHY3_RGMII_RXD3: R565.2 U97.2(A2)
PHY3_RGMII_TX_EN: U34.19(TXCTL) U99.2(A2)
PHY3_RGMII_TXC: U34.20(TXC) U100.1(A1)
PHY3_RGMII_TXD0: U34.18(TXD0) U98.2(A2)
PHY3_RGMII_TXD1: U34.17(TXD1) U99.1(A1)
PHY3_RGMII_TXD2: U34.16(TXD2) U96.2(A2)
PHY3_RGMII_TXD3: U34.15(TXD3) U96.1(A1)
PHY3_TRX0_N: J31.3(TRD1-) U32.2(CH2) U32.9(NC3) U34.2(MDIN0)
PHY3_TRX0_P: J31.2(TRD1+) U32.1(CH1) U32.10(NC4) U34.1(MDIP0)
PHY3_TRX1_N: J31.5(TRD2-) U32.5(CH4) U32.6(NC1) U34.5(MDIN1)
PHY3_TRX1_P: J31.4(TRD2+) U32.4(CH3) U32.7(NC2) U34.4(MDIP1)
PHY3_TRX2_N: J31.7(TRD3-) U33.2(CH2) U33.9(NC3) U34.7(MDIN2)
PHY3_TRX2_P: J31.6(TRD3+) U33.1(CH1) U33.10(NC4) U34.6(MDIP2)
PHY3_TRX3_N: J31.9(TRD4-) U33.5(CH4) U33.6(NC1) U34.10(MDIN3)
PHY3_TRX3_P: J31.8(TRD4+) U33.4(CH3) U33.7(NC2) U34.9(MDIP3)
PHY3_XTALI: C229.1 U34.36(XTAL_IN) X3.3
PHY3_XTALO: C228.1 U34.37(XTAL_OUT/_EXT_CLK) X3.1
RXC_PHYAD1_1: R431.2 R443.1 R462.1 U27.27(RXC/PHYAD1)
RXC_PHYAD1_2: R475.2 R498.1 R515.1 U29.27(RXC/PHYAD1)
RXC_PHYAD1_3: R527.2 R550.1 R568.1 U34.27(RXC/PHYAD1)
RXCTL_PHYAD2_1: R432.1 R444.2 R463.1 U27.26(RXCTL/PHYAD2)
RXCTL_PHYAD2_2: R476.2 R499.1 R516.1 U29.26(RXCTL/PHYAD2)
RXCTL_PHYAD2_3: R528.1 R551.2 R569.1 U34.26(RXCTL/PHYAD2)
RXD0_RXDLY_1: R429.2 R441.1 R458.1 U27.25(RXD0/RXDLY)
RXD0_RXDLY_2: R473.2 R496.1 R514.1 U29.25(RXD0/RXDLY)
RXD0_RXDLY_3: R525.2 R548.1 R564.1 U34.25(RXD0/RXDLY)
RXD1_TXDLY_1: R428.2 R440.1 R460.1 U27.24(RXD1/TXDLY)
RXD1_TXDLY_2: R472.2 R495.1 R511.1 U29.24(RXD1/TXDLY)
RXD1_TXDLY_3: R524.2 R547.1 R566.1 U34.24(RXD1/TXDLY)
RXD2_PLLOFF_1: R433.2 R445.1 R459.1 U27.23(RXD2/PLLOFF)
RXD2_PLLOFF_2: R477.2 R500.1 R512.1 U29.23(RXD2/PLLOFF)
RXD2_PLLOFF_3: R529.2 R552.1 R567.1 U34.23(RXD2/PLLOFF)
RXD3_PHYAD0_1: R430.2 R442.1 R461.1 U27.22(RXD3/PHYAD0)
RXD3_PHYAD0_2: R474.2 R497.1 R513.1 U29.22(RXD3/PHYAD0)
RXD3_PHYAD0_3: R526.2 R549.1 R565.1 U34.22(RXD3/PHYAD0)
SENSOR_3V3: C431.1 C432.1 C433.1 C434.1 C435.1 C436.1 C452.1 C455.1 C908.1 J63.1 J65.1 J72.1 J73.1 R455.2 R456.2 R464.1 R469.1 R508.2 R509.2 R510.2 R517.1 R522.1 R561.2 R562.2 R563.2 R570.1 R575.1 U96.10(VCC) U97.10(VCC) U98.10(VCC) U99.10(VCC) U100.10(VCC) U101.10(VCC) U103.10(VCC) U106.10(VCC) U416.5(VCC) ; also on sheet 2 5 6 7 8 9 10 11 12 13 14 15 19 20 21 22 23 24 25 26 27 28 29 30 31
N100999218: C203.1 C204.1 R468.1 R470.1 U27.30(REG_OUT/LDO_OUT)
N101003766: R465.1 U27.31(~{INT}/~{PME})
N101003882: C202.1 R466.1 U27.35(CLKOUT)
N101004896: R469.2 U27.12(~{PHYRST}) U410.4(Y)
N101006850: J29.13 R449.1
N101006888: J29.11 R452.1
N101007093: R467.1 U27.39(RSET)
N103749857: C225.1 C226.1 R521.1 R523.1 U29.30(REG_OUT/LDO_OUT)
N103749903: R518.1 U29.31(~{INT}/~{PME})
N103749907: C224.1 R519.1 U29.35(CLKOUT)
N103750002: J30.13 R505.1
N103750008: J30.11 R506.1
N103750009: R520.1 U29.39(RSET)
N103753894: C247.1 C248.1 R574.1 R576.1 U34.30(REG_OUT/LDO_OUT)
N103753940: R571.1 U34.31(~{INT}/~{PME})
N103753944: C246.1 R572.1 U34.35(CLKOUT)
N103754039: J31.13 R558.1
N103754045: J31.11 R559.1
N103754046: R573.1 U34.39(RSET)
N105847330: R446.2 R448.2 U125.8(B1)
N105847333: R450.2 R453.2 U125.1(B2)
N105847380: R1319.2 U125.6(OE)
N107062928: R464.2 R465.2 U416.2(A)

Not connected (* = marked no-connect by the designer): U410 1(NC)*; U416 1(NC)*

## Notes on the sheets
sheet 16
- SOC RGMII 1.8V SIGNALS
- CFG_EXT
  EXTERNAL: 1(Default)
  INTERNAL: 0
- Pull-up for additional 2ns delay to
  TXC/RXC for data latching.
- TXC Delay Config
- CFG_LDO[1:0]
  1.8V: 10 (Default)
  2.5V: 01
  3.3V: 00
- RXC Delay Config
- PHY_ADDR0
- PHY_ADDR1
- PHY_ADDR2
- PHY_ADDR: 101
- Pull-up to disable PLL @ ALDPS mode.
- (Reserved for EMI, opt)
sheet 17
- SEL_0  COM to A Port
  SEL_1  COM to B Port
- Default: 2-3
- Default: 2-3
- Pull-up for additional 2ns delay to
  TXC/RXC for data latching.
- CFG_EXT
  EXTERNAL: 1(Default)
  INTERNAL: 0
- TXC Delay Config
- RXC Delay Config
- PHY_ADDR0
- PHY_ADDR1
- CFG_LDO[1:0]
  1.8V: 10
  2.5V: 01
  3.3V: 00 (Default)
- PHY_ADDR2
- PHY_ADDR: 100
- Pull-up to disable PLL @ ALDPS mode.
- (Reserved for EMI, opt)
sheet 18
- SEL_0  COM to A Port
  SEL_1  COM to B Port
- Pull-up for additional 2ns delay to
  TXC/RXC for data latching.
- TXC Delay Config
- RXC Delay Config
- PHY_ADDR0
- PHY_ADDR1
- PHY_ADDR2
- PHY_ADDR: 111
- Default: 2-3
- Pull-up to disable PLL @ ALDPS mode.
- Default: 2-3
- CFG_EXT
  EXTERNAL: 1(Default)
  INTERNAL: 0
- CFG_LDO[1:0]
  1.8V: 10
  2.5V: 01
  3.3V: 00(Default)
- (Reserved for EMI, opt)
